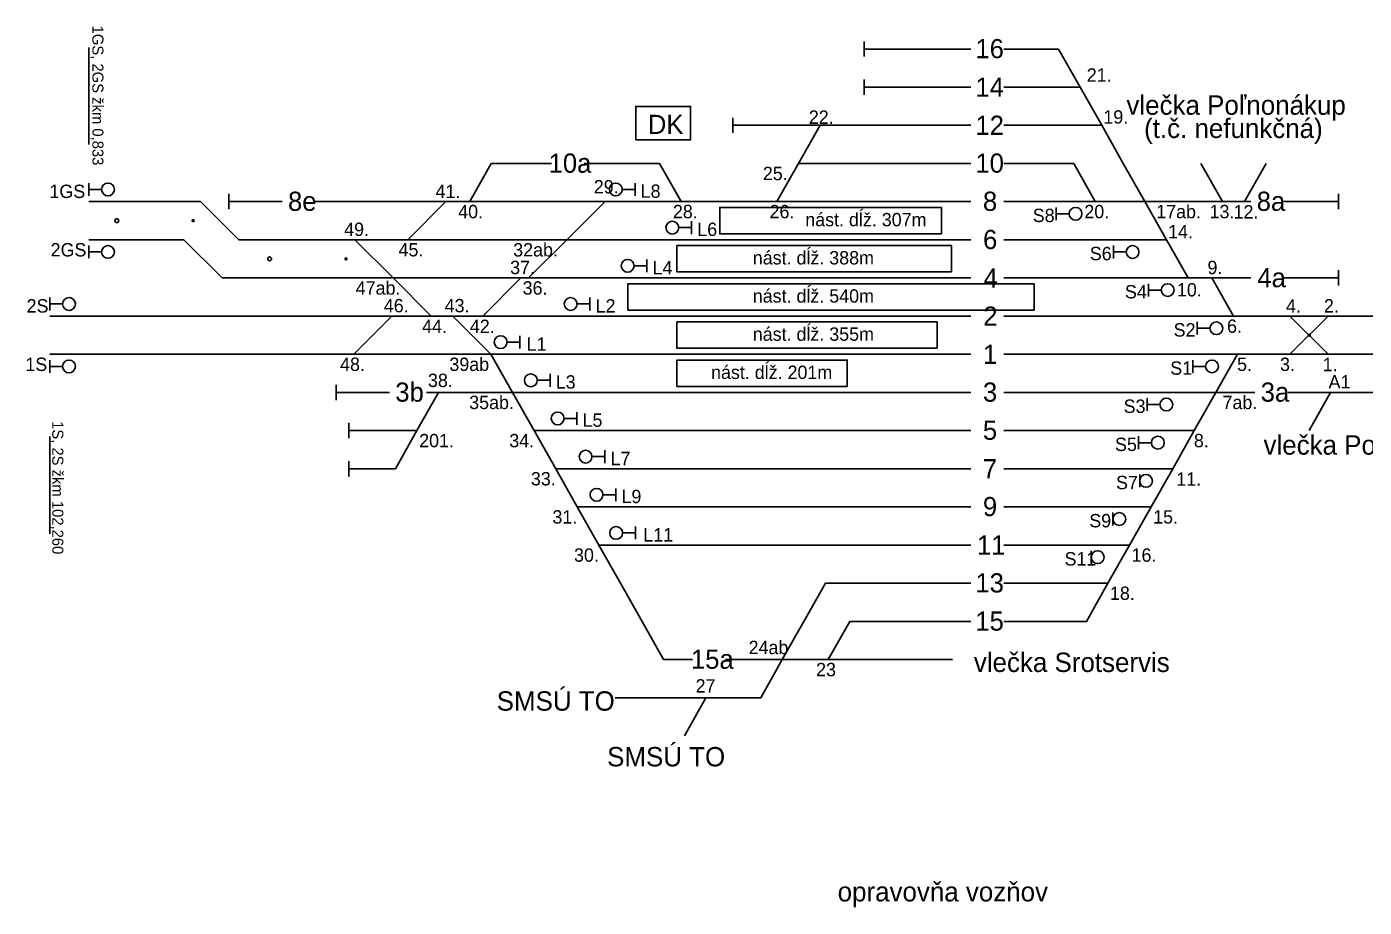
# Model space of a CAD drawing. Extents: x -119 to 851, y -238 to 59.
# Drawn here: x -83.3 to -13.2, y -138.3 to -92.2 of the extents above; entities that cross this region are included whole.
import ezdxf

# ---------------------------------------------------------------- set-up
doc = ezdxf.new("R2010")
doc.units = 0
for name, color, linetype in [('budova', 7, 'Continuous'), ('Level 2', 7, 'Continuous'), ('nastupistia', 7, 'Continuous'), ('netlač', 7, 'Continuous'), ('popisky navestidla', 7, 'Continuous'), ('PU_navestidla', 7, 'Continuous'), ('PU_oznacenie navestidiel', 7, 'Continuous'), ('PU_stan_kolaje', 7, 'Continuous'), ('PU_vlecky', 7, 'Continuous'), ('schema_km0-1_0-2', 7, 'Continuous')]:
    doc.layers.add(name, color=color, linetype=linetype)

msp = doc.modelspace()

# ---------------------------------------------------------------- linework, layer by layer
at = {"layer": 'budova'}
msp.add_lwpolyline([(-51.363, -98.07), (-48.495, -98.07), (-48.495, -96.322), (-51.363, -96.322)], close=True, dxfattribs=at)
at = {"layer": 'Level 2'}
for p, q in [((-39.398, -93.715), (-39.398, -92.916)), ((-39.398, -95.714), (-39.398, -94.914)), ((-46.281, -97.712), (-46.281, -96.913)), ((-72.68, -101.707), (-72.68, -100.908)), ((-57.794, -101.307), (-52.977, -101.307)), ((-52.469, -101.307), (-47.222, -101.307)), ((-47.222, -101.307), (-33.813, -101.307)), ((-14.56, -101.707), (-14.56, -100.908)), ((-14.56, -105.706), (-14.56, -104.907)), ((-82.053, -107.305), (-64.985, -107.305)), ((-64.985, -107.305), (-48.787, -107.305)), ((-48.787, -107.305), (-33.813, -107.305)), ((-32.089, -107.305), (-25.19, -107.305)), ((-25.19, -107.305), (-1.993, -107.305)), ((-82.053, -109.304), (-49.987, -109.304)), ((-49.987, -109.304), (-33.813, -109.304)), ((-32.089, -109.304), (-24.19, -109.304)), ((-24.19, -109.304), (-5.893, -109.304)), ((-67.059, -111.702), (-67.059, -110.903)), ((-66.392, -113.701), (-66.392, -112.901)), ((-66.392, -115.699), (-66.392, -114.899))]:
    msp.add_line(p, q, dxfattribs=at)
for points in [[(-72.68, -101.307), (-69.887, -101.307)], [(-68.163, -101.307), (-57.794, -101.307)], [(-52.977, -101.307), (-52.469, -101.307)], [(-32.089, -101.309), (-24.701, -101.309)], [(-67.059, -111.302), (-64.266, -111.302)], [(-62.331, -111.302), (-57.794, -111.302)], [(-66.392, -113.301), (-62.827, -113.301)], [(-66.392, -115.299), (-63.957, -115.299)]]:
    msp.add_lwpolyline(points, dxfattribs=at)
at = {"layer": 'nastupistia'}
for points in [[(-35.354, -102.997), (-46.968, -102.997), (-46.968, -101.612), (-35.354, -101.612)], [(-34.837, -104.994), (-49.207, -104.994), (-49.207, -103.61), (-34.837, -103.61)], [(-30.505, -106.993), (-51.779, -106.993), (-51.779, -105.608), (-30.505, -105.608)], [(-35.58, -108.992), (-49.207, -108.992), (-49.207, -107.607), (-35.58, -107.607)], [(-40.289, -110.991), (-49.207, -110.991), (-49.207, -109.606), (-40.289, -109.606)]]:
    msp.add_lwpolyline(points, close=True, dxfattribs=at)
at = {"layer": 'netlač'}
for p, q in [((-33.813, -93.316), (-39.398, -93.316)), ((-29.221, -93.316), (-32.089, -93.316)), ((-33.813, -95.314), (-39.398, -95.314)), ((-28.091, -95.314), (-32.089, -95.314)), ((-41.71, -97.313), (-46.281, -97.313)), ((-33.813, -97.313), (-41.71, -97.313)), ((-26.961, -97.313), (-32.089, -97.313)), ((-55.787, -99.311), (-58.933, -99.311)), ((-50.119, -99.311), (-54.063, -99.311)), ((-33.813, -99.311), (-42.84, -99.311)), ((-28.431, -99.311), (-32.089, -99.311)), ((-74.16, -101.308), (-80.018, -101.308)), ((-24.702, -101.307), (-19.152, -101.307)), ((-17.429, -101.307), (-14.56, -101.307)), ((-75.029, -103.308), (-80.018, -103.308)), ((-33.813, -103.308), (-72.161, -103.308)), ((-23.571, -103.308), (-32.089, -103.308)), ((-73.031, -105.305), (-33.813, -105.305)), ((-21.194, -105.306), (-32.089, -105.306)), ((-21.194, -105.306), (-19.152, -105.306)), ((-17.429, -105.306), (-14.56, -105.306)), ((-33.813, -111.302), (-57.819, -111.302)), ((-20.986, -111.302), (-32.089, -111.302)), ((-20.986, -111.302), (-18.944, -111.302)), ((-17.221, -111.302), (-7.894, -111.302)), ((-33.813, -113.301), (-56.689, -113.301)), ((-22.116, -113.301), (-32.089, -113.301)), ((-33.813, -115.299), (-55.559, -115.299)), ((-23.246, -115.299), (-32.089, -115.299)), ((-33.813, -117.298), (-54.429, -117.298)), ((-24.376, -117.298), (-32.089, -117.298)), ((-33.813, -119.296), (-53.299, -119.296)), ((-25.506, -119.296), (-32.089, -119.296)), ((-33.813, -121.295), (-41.431, -121.295)), ((-26.635, -121.295), (-32.089, -121.295)), ((-33.813, -123.293), (-40.156, -123.293)), ((-27.765, -123.293), (-32.089, -123.293)), ((-48.387, -125.292), (-49.909, -125.292)), ((-41.286, -125.292), (-46.663, -125.292)), ((-41.286, -125.292), (-34.782, -125.292)), ((-44.821, -127.29), (-52.439, -127.29))]:
    msp.add_line(p, q, dxfattribs=at)
at = {"layer": 'popisky navestidla'}
for p, q in [((-80.018, -98.324), (-80.018, -93.233)), ((-82.053, -113.617), (-82.053, -118.708))]:
    msp.add_line(p, q, dxfattribs=at)
at = {"layer": 'PU_navestidla'}
for p, q in [((-80.018, -100.335), (-80.018, -101.007)), ((-80.018, -100.672), (-79.346, -100.672)), ((-51.405, -100.674), (-52.077, -100.674)), ((-51.405, -100.336), (-51.405, -101.008)), ((-29.34, -102.281), (-29.34, -101.609)), ((-29.34, -101.944), (-28.668, -101.944)), ((-48.444, -102.673), (-49.116, -102.673)), ((-48.444, -102.335), (-48.444, -103.007)), ((-80.018, -104.279), (-80.018, -103.607)), ((-26.354, -104.28), (-26.354, -103.608)), ((-80.018, -103.942), (-79.346, -103.942)), ((-50.785, -104.334), (-50.785, -105.006)), ((-26.354, -103.943), (-25.682, -103.943)), ((-50.785, -104.671), (-51.457, -104.671)), ((-24.514, -106.278), (-24.514, -105.606)), ((-82.053, -106.333), (-82.053, -107.005)), ((-53.77, -106.333), (-53.77, -107.005)), ((-24.514, -105.941), (-23.842, -105.941)), ((-82.053, -106.67), (-81.381, -106.67)), ((-53.77, -106.67), (-54.442, -106.67)), ((-21.966, -108.277), (-21.966, -107.605)), ((-57.434, -108.332), (-57.434, -109.004)), ((-21.966, -107.939), (-21.294, -107.939)), ((-57.434, -108.669), (-58.106, -108.669)), ((-82.053, -110.277), (-82.053, -109.605)), ((-82.053, -109.94), (-81.381, -109.94)), ((-22.196, -110.276), (-22.196, -109.604)), ((-22.196, -109.938), (-21.524, -109.938)), ((-55.855, -110.668), (-56.527, -110.668)), ((-55.855, -110.33), (-55.855, -111.002)), ((-24.583, -112.274), (-24.583, -111.602)), ((-24.583, -111.937), (-23.911, -111.937)), ((-54.45, -112.666), (-55.122, -112.666)), ((-54.45, -112.329), (-54.45, -113.001)), ((-25.03, -114.273), (-25.03, -113.601)), ((-25.03, -113.935), (-24.358, -113.935)), ((-52.986, -114.665), (-53.658, -114.665)), ((-52.986, -114.327), (-52.986, -114.999)), ((-24.975, -116.271), (-24.975, -115.599)), ((-52.411, -116.663), (-53.083, -116.663)), ((-52.411, -116.326), (-52.411, -116.998)), ((-26.379, -118.268), (-26.379, -117.596)), ((-51.385, -118.324), (-51.385, -118.996)), ((-51.385, -118.662), (-52.057, -118.662)), ((-27.509, -120.267), (-27.509, -119.595))]:
    msp.add_line(p, q, dxfattribs=at)
for centre in [(-79.01, -100.671), (-52.413, -100.672), (-28.332, -101.945), (-49.452, -102.671), (-79.01, -103.943), (-25.346, -103.944), (-51.793, -104.67), (-23.506, -105.942), (-81.045, -106.669), (-54.778, -106.669), (-20.958, -107.941), (-58.442, -108.668), (-81.045, -109.941), (-21.188, -109.94), (-56.863, -110.666), (-23.575, -111.938), (-55.458, -112.665), (-24.022, -113.937), (-53.994, -114.663), (-24.639, -115.935), (-53.419, -116.662), (-26.043, -117.932), (-52.393, -118.66), (-27.173, -119.931)]:
    msp.add_circle(centre, 0.336, dxfattribs=at)
at = {"layer": 'PU_stan_kolaje'}
for points in [[(-29.221, -93.316), (-28.091, -95.314)], [(-28.091, -95.314), (-26.961, -97.313)], [(-42.84, -99.311), (-41.71, -97.313)], [(-26.961, -97.313), (-25.831, -99.311)], [(-60.063, -101.309), (-58.933, -99.311)], [(-50.119, -99.311), (-48.989, -101.309)], [(-43.97, -101.309), (-42.84, -99.311)], [(-28.431, -99.311), (-27.301, -101.309)], [(-25.831, -99.311), (-24.701, -101.309)], [(-21.764, -99.309), (-20.634, -101.307)], [(-19.484, -101.307), (-18.354, -99.309)], [(-74.16, -101.308), (-72.161, -103.307)], [(-61.313, -101.307), (-63.312, -103.306)], [(-52.977, -101.307), (-54.976, -103.306)], [(-24.701, -101.309), (-23.571, -103.308)], [(-75.029, -103.307), (-73.03, -105.306)], [(-66.073, -103.307), (-64.074, -105.306)], [(-54.976, -103.306), (-56.975, -105.305)], [(-23.571, -103.308), (-22.441, -105.306)], [(-64.074, -105.306), (-62.075, -107.305)], [(-57.381, -105.305), (-59.38, -107.304)], [(-21.194, -105.306), (-20.064, -107.305)], [(-64.135, -107.305), (-66.134, -109.304)], [(-60.948, -107.305), (-58.949, -109.304)], [(-17.105, -107.305), (-15.106, -109.304)], [(-15.106, -107.305), (-17.105, -109.304)], [(-57.819, -111.302), (-58.949, -109.304)], [(-20.986, -111.302), (-19.856, -109.304)], [(-62.827, -113.301), (-61.697, -111.302)], [(-56.689, -113.301), (-57.819, -111.302)], [(-22.116, -113.301), (-20.986, -111.302)], [(-16.104, -113.301), (-14.974, -111.302)], [(-63.957, -115.299), (-62.827, -113.301)], [(-55.559, -115.299), (-56.689, -113.301)], [(-23.246, -115.299), (-22.116, -113.301)], [(-54.429, -117.298), (-55.559, -115.299)], [(-24.376, -117.298), (-23.246, -115.299)], [(-53.299, -119.296), (-54.429, -117.298)], [(-25.506, -119.296), (-24.376, -117.298)], [(-52.169, -121.295), (-53.299, -119.296)], [(-26.635, -121.295), (-25.506, -119.296)], [(-51.039, -123.293), (-52.169, -121.295)], [(-42.561, -123.293), (-41.431, -121.295)], [(-27.765, -123.293), (-26.635, -121.295)], [(-49.909, -125.292), (-51.039, -123.293)], [(-43.691, -125.292), (-42.561, -123.293)], [(-41.286, -125.292), (-40.156, -123.293)], [(-44.821, -127.29), (-43.691, -125.292)], [(-48.822, -129.289), (-47.692, -127.29)]]:
    msp.add_lwpolyline(points, dxfattribs=at)
at = {"layer": 'schema_km0-1_0-2'}
for centre, radius in [((-78.54, -102.307), 0.1), ((-74.541, -102.307), 0.0502), ((-70.541, -104.307), 0.1), ((-66.542, -104.307), 0.0502), ((-16.088, -108.305), 0.0502)]:
    msp.add_circle(centre, radius, dxfattribs=at)

# ---------------------------------------------------------------- texts
at = {"layer": 'budova'}
msp.add_text('DK', height=1.0044, dxfattribs=at).set_placement((-50.733, -97.766))
at = {"layer": 'nastupistia'}
for s, p in [('nást. dĺž. 307m', (-42.488, -102.602)), ('nást. dĺž. 388m', (-45.238, -104.6)), ('nást. dĺž. 540m', (-45.238, -106.599)), ('nást. dĺž. 355m', (-45.238, -108.598)), ('nást. dĺž. 201m', (-47.423, -110.597))]:
    msp.add_text(s, height=0.7, dxfattribs=at).set_placement(p)
at = {"layer": 'popisky navestidla'}
for s, p in [('1GS, 2GS žkm 0,833', (-79.825, -92.091)), ('1S, 2S žkm 102,260', (-81.924, -112.805))]:
    msp.add_text(s, height=0.57931, rotation=270, dxfattribs=at).set_placement(p)
at = {"layer": 'PU_oznacenie navestidiel'}
for s, p in [('21.', (-27.747, -95.028)), ('22.', (-42.303, -97.236)), ('19.', (-26.876, -97.224)), ('25.', (-44.711, -100.185)), ('1GS', (-82.074, -101.121)), ('41.', (-61.854, -101.122)), ('29.', (-53.564, -100.881)), ('L8', (-51.108, -101.11)), ('40.', (-60.666, -102.181)), ('28.', (-49.422, -102.181)), ('26.', (-44.358, -102.181)), ('20.', (-27.872, -102.181)), ('17ab.', (-24.108, -102.181)), ('13.', (-21.313, -102.181)), ('12.', (-20.059, -102.193)), ('S8', (-30.574, -102.381)), ('49.', (-66.637, -103.11)), ('L6', (-48.145, -103.109)), ('14.', (-23.486, -103.232)), ('2GS', (-82.011, -104.182)), ('45.', (-63.792, -104.18)), ('32ab.', (-57.785, -104.183)), ('S6', (-27.587, -104.379)), ('37.', (-57.945, -105.107)), ('L4', (-50.486, -105.12)), ('9.', (-21.422, -105.108)), ('47ab.', (-66.032, -106.181)), ('36.', (-57.291, -106.181)), ('S4', (-25.746, -106.378)), ('10.', (-23.023, -106.275)), ('2S', (-83.27, -107.119)), ('46.', (-64.563, -107.107)), ('43.', (-61.376, -107.107)), ('L2', (-53.469, -107.119)), ('4.', (-17.31, -107.119)), ('2.', (-15.324, -107.119)), ('44.', (-62.555, -108.191)), ('42.', (-60.055, -108.191)), ('S2', (-23.196, -108.376)), ('6.', (-20.399, -108.179)), ('L1', (-57.08, -109.118)), ('1S', (-83.333, -110.18)), ('48.', (-66.852, -110.178)), ('39ab', (-61.126, -110.178)), ('S1', (-23.373, -110.375)), ('5.', (-19.875, -110.178)), ('3.', (-17.623, -110.178)), ('1.', (-15.388, -110.19)), ('38.', (-62.25, -111.019)), ('L3', (-55.556, -111.104)), ('A1', (-15.081, -111.096)), ('35ab.', (-60.09, -112.176)), ('S3', (-25.815, -112.374)), ('7ab.', (-20.636, -112.176)), ('L5', (-54.154, -113.103)), ('201.', (-62.71, -114.175)), ('34.', (-57.99, -114.175)), ('8.', (-22.135, -114.175)), ('S5', (-26.265, -114.372)), ('L7', (-52.687, -115.113)), ('33.', (-56.86, -116.173)), ('11.', (-23.056, -116.185)), ('S7', (-26.211, -116.371)), ('L9', (-52.113, -117.1)), ('31.', (-55.73, -118.172)), ('S9', (-27.613, -118.369)), ('15.', (-24.27, -118.172)), ('L11', (-50.974, -119.11)), ('30.', (-54.6, -120.17)), ('S11', (-28.91, -120.368)), ('16.', (-25.4, -120.17)), ('18.', (-26.53, -122.169)), ('24ab', (-45.456, -125.01)), ('23', (-41.921, -126.166)), ('27', (-48.232, -127.02))]:
    msp.add_text(s, height=0.7, dxfattribs=at).set_placement(p)
at = {"layer": 'PU_stan_kolaje'}
for s, height, p in [('16', 1.0044, (-33.579, -93.799)), ('14', 1.0044, (-33.579, -95.814)), ('12', 1.0044, (-33.576, -97.813)), ('10a', 1.0044, (-55.931, -99.796)), ('10', 1.0044, (-33.579, -99.794)), ('8e', 1.0044, (-69.579, -101.792)), ('8', 1.004, (-33.184, -101.792)), ('8a', 1.0044, (-18.845, -101.792)), ('6', 1.004, (-33.178, -103.793)), ('4', 1.004, (-33.149, -105.809)), ('4a', 1.0044, (-18.812, -105.792)), ('2', 1.004, (-33.166, -107.807)), ('1', 1.004, (-33.18, -109.806)), ('3b', 1.0044, (-63.959, -111.787)), ('3', 1.004, (-33.183, -111.787)), ('3a', 1.0044, (-18.636, -111.787)), ('5', 1.004, (-33.186, -113.786)), ('7', 1.004, (-33.19, -115.801)), ('9', 1.004, (-33.184, -117.783)), ('11', 1.0044, (-33.5, -119.798)), ('13', 1.0044, (-33.579, -121.78)), ('15', 1.0044, (-33.583, -123.778)), ('15a', 1.0044, (-48.476, -125.777))]:
    msp.add_text(s, height=height, dxfattribs=at).set_placement(p)
at = {"layer": 'PU_vlecky'}
for s, p in [('vlečka Poľnonákup', (-25.667, -96.76)), ('(t.č. nefunkčná)', (-24.743, -97.978)), ('vlečka Poľnonákup', (-18.487, -114.561)), ('vlečka Srotservis', (-33.659, -125.944)), ('SMSÚ TO', (-58.649, -127.97)), ('SMSÚ TO', (-52.866, -130.889)), ('opravovňa vozňov', (-40.792, -137.959))]:
    msp.add_text(s, height=1.015, dxfattribs=at).set_placement(p)

doc.saveas('drawing.dxf')
